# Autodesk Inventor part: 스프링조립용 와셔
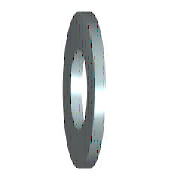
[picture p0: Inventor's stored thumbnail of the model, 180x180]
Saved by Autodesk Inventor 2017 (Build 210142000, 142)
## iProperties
IsCustomPart: 1
Created: 2012-02
Part Number: 스프링조립용 와셔
Material: 강철, 연강
Description: 평면 와셔
Document SubType Name: Modeling
Standard: KS B 1326
Designer: mduedu
Standards Organization: KS
Language: ko-KR
Size Designation: 12x24
Categories: <MemberInstance><Categories><Category DisplayName="조임쇠" InternalName="e4da775c-781d-43d5-af7c-5136215cf5a6" Mnemonic="FSTN"><Category DisplayName="와셔" InternalN
Density: 7.85 g/cm^3
Appearance: 강철
Mass: 5.38854 g
Surface Area: 8.71478 cm^2
Volume: 0.686438 cm^3
Author: mduedu
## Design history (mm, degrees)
sketch "스케치"
  geometry: C1 r 12 at (0, 0); C2 r 7 at (0, 0); 1 further point
  constraints: 2 centre point, 2 coincident
  dimensions: "d0" = 14 diameter of C2 (= SD1); "d1" = 24 diameter of C1 (= SD2)
extrude "본체" new body sketch "스케치" distance "d2" = 2.3 (= SD); taper "d3" = 0 deg
workaxis "Work Axis1"
workplane "Work Plane1"
body "Solid1"
other parameters: "SD1" = 14 [user parameter; used in 1 equation term], "SD2" = 24 [user parameter; used in 1 equation term], "SD" = 2.3 [user parameter; used in 1 equation term], "d4" = 0, "d5" = 0, "d6" = 0, "d7" = 0, "NND" = 12 [user parameter]
